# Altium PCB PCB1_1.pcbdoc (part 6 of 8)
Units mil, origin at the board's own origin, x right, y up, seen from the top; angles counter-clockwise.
Board outline 3937.01 x 3346.46 mil, 6 copper layers (Top Layer, Signal-1, SIG, POWER, Signal-4, Bottom Layer), stack 60.565 mil thick; 256 components, 201 nets, 1360 pads, 815 vias.
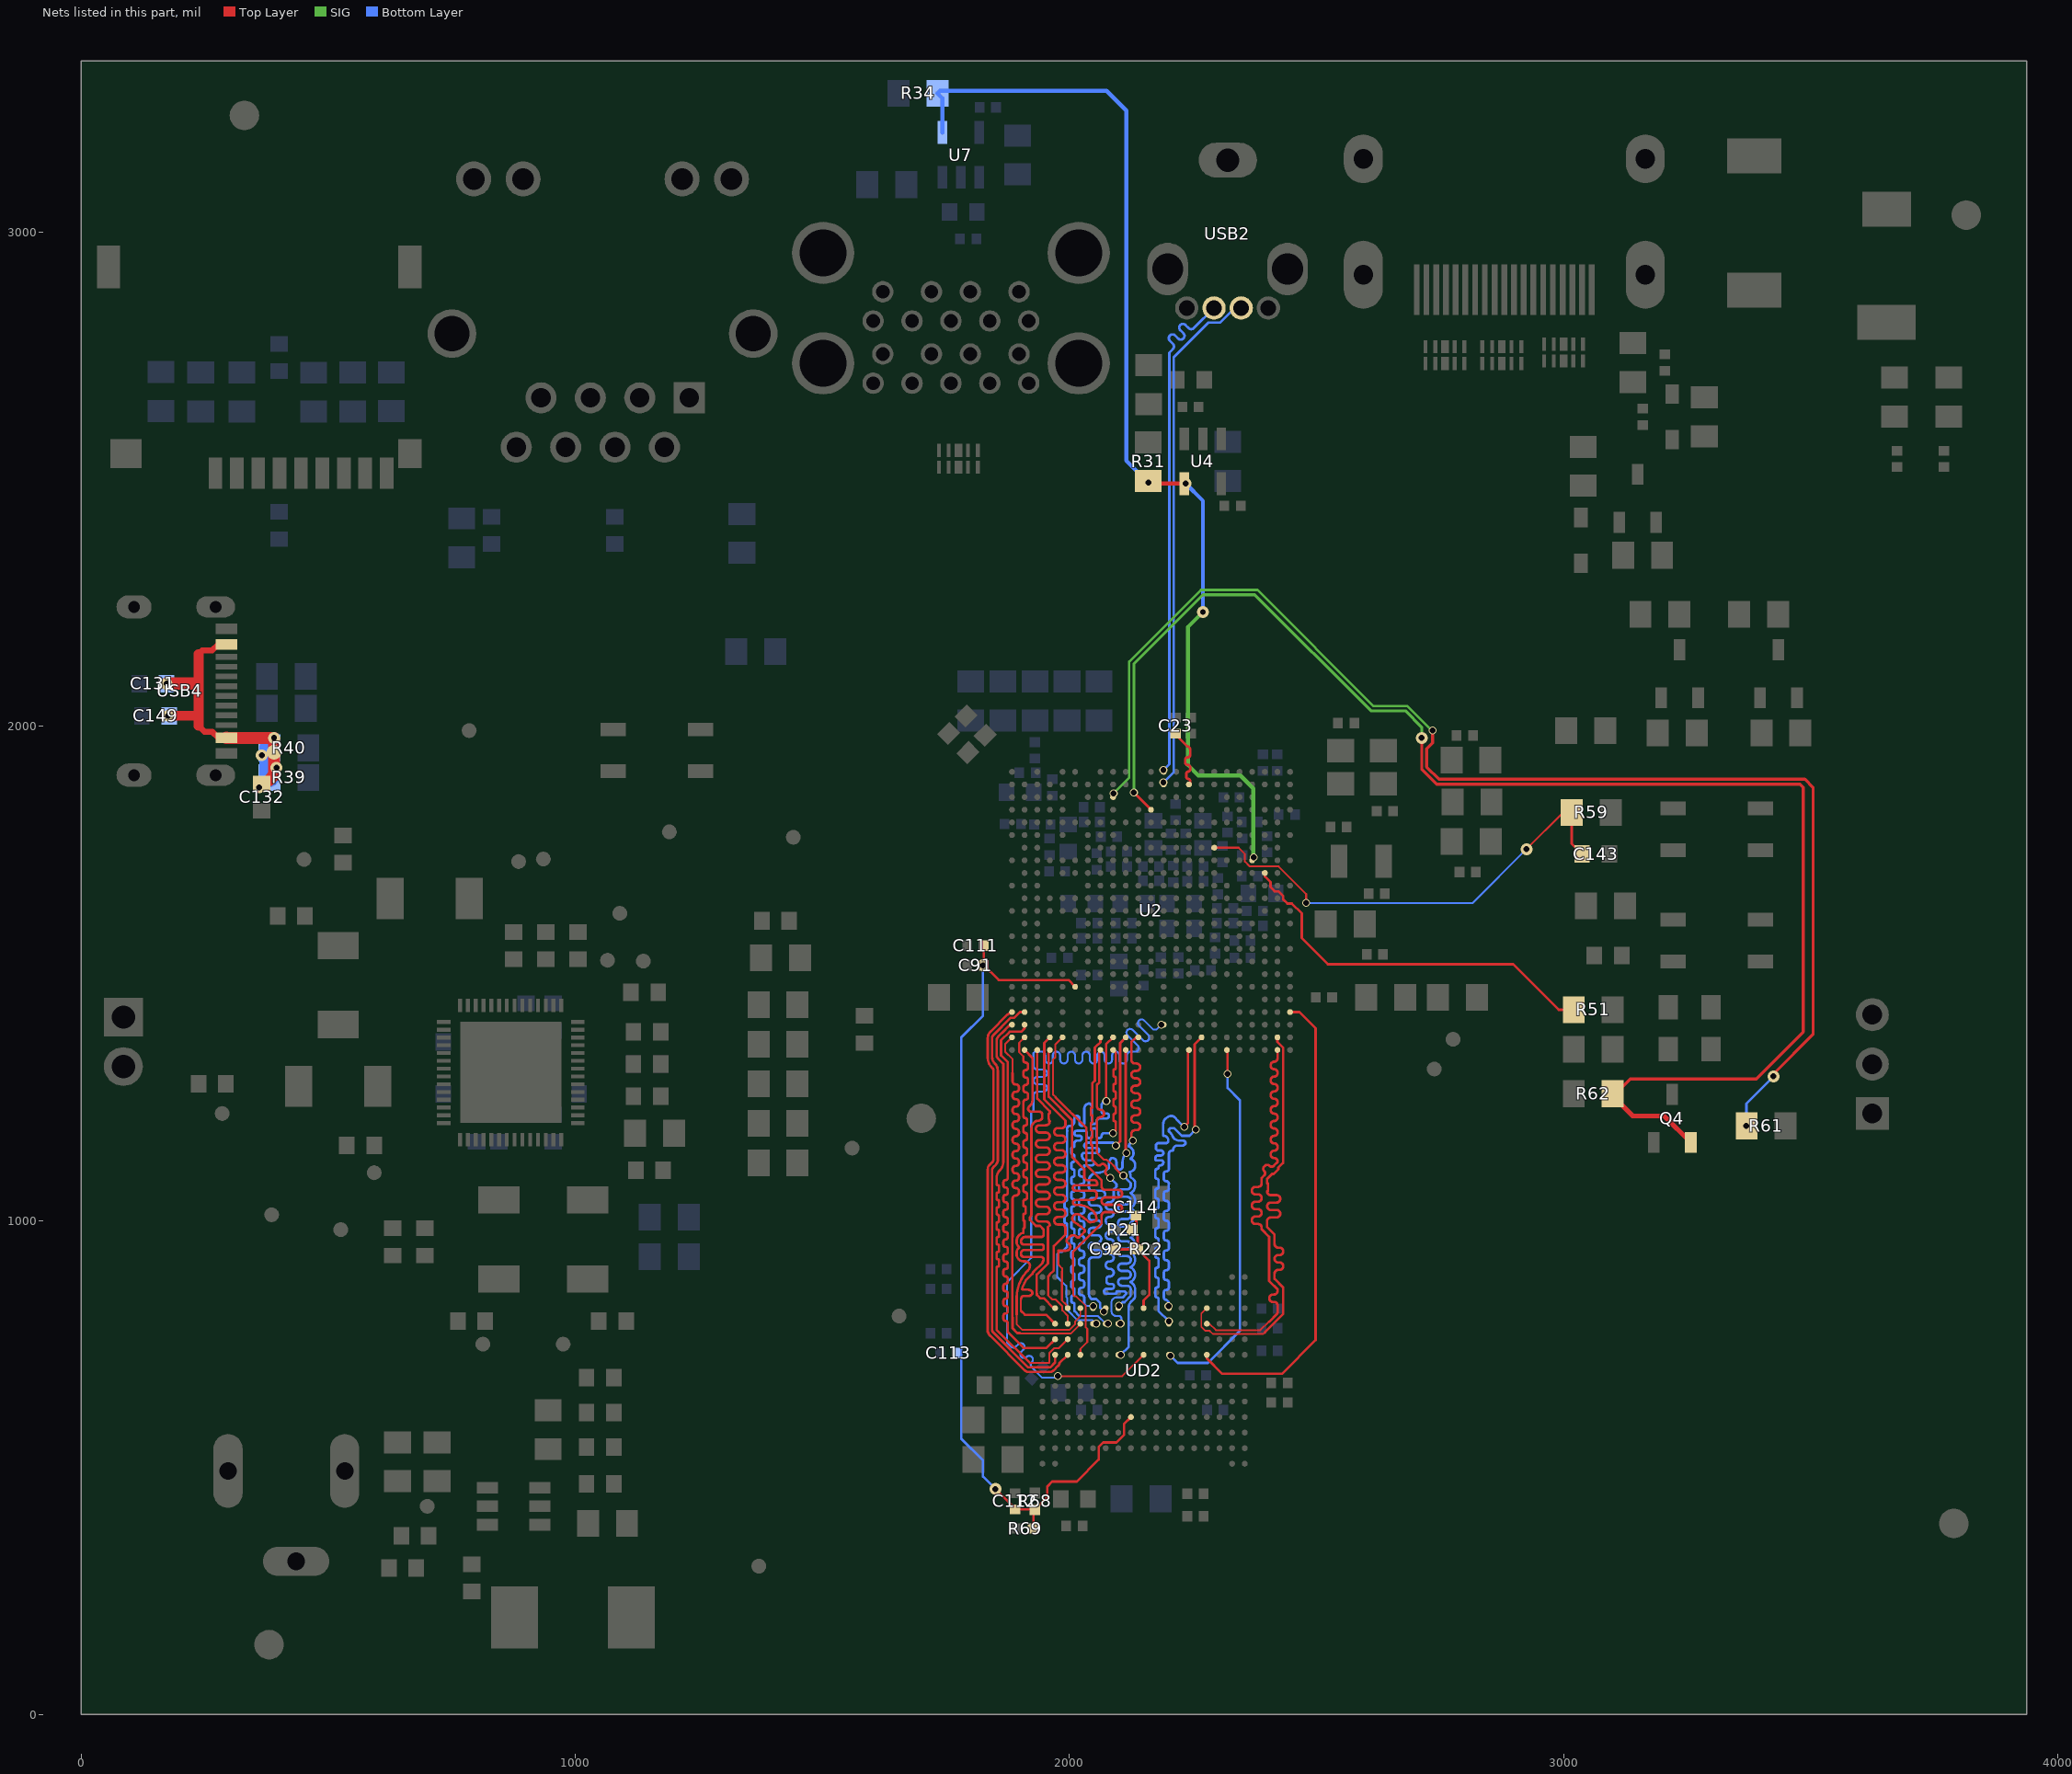
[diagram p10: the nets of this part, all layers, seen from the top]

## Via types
v1: diameter 16, hole 12, Top Layer to Bottom Layer, 426 vias
v2: diameter 24, hole 12, Top Layer to Bottom Layer, 385 vias
v3: diameter 34, hole 12, Top Layer to Bottom Layer, 2 vias
v4: diameter 30, hole 12, Top Layer to Bottom Layer, 2 vias

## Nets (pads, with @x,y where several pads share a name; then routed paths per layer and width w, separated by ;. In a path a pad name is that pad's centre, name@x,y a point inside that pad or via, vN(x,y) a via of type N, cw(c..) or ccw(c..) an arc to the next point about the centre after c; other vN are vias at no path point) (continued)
SDQ20: U2.AC9 UD2.F10 | length 857.1
  Top Layer w5: U2.AC9@2088.23,1344.96 2093.41,1339.78 2093.41,1308.09 cw(c2091.26,1308.09) 2091.26,1305.94 ccw(c2091.26,1303.78) 2089.1,1303.78 2089.1,1293.09 ccw(c2091.26,1293.09) 2091.26,1290.94 cw(c2091.26,1288.78) 2093.41,1288.78 2093.41,1278.09 cw(c2091.26,1278.09) 2091.26,1275.94 ccw(c2091.26,1273.78) 2089.1,1273.78 2089.1,1263.09 ccw(c2091.26,1263.09) 2091.26,1260.94 cw(c2091.26,1258.78) 2093.41,1258.78 2093.41,1248.09 cw(c2091.26,1248.09) 2091.26,1245.94 ccw(c2091.26,1243.78) 2089.1,1243.78 2089.1,1233.09 ccw(c2091.26,1233.09) 2091.26,1230.94 cw(c2091.26,1228.78) 2093.41,1228.78 2093.41,1218.09 cw(c2091.26,1218.09) 2091.26,1215.94 ccw(c2091.26,1213.78) 2089.1,1213.78 2089.1,1203.09 ccw(c2091.26,1203.09) 2091.26,1200.94 cw(c2091.26,1198.78) 2093.41,1198.78 2093.41,1181.46 v1(2088.41,1176.46)
  Bottom Layer w4: 2020,806.46 2057.63,806.46 2073.14,790.94 v1(2078.23,790.94)
  Bottom Layer w5: 2020,806.46 2010,816.46 2010,830.28 ccw(c2007,830.28) 2007,833.28 cw(c2007,836.28) 2004,836.28 2004,845.28 cw(c2007,845.28) 2007,848.28 ccw(c2007,851.28) 2010,851.28 2010,860.28 ccw(c2007,860.28) 2007,863.28 cw(c2007,866.28) 2004,866.28 2004,875.28 cw(c2007,875.28) 2007,878.28 ccw(c2007,881.28) 2010,881.28 2010,890.28 ccw(c2007,890.28) 2007,893.28 cw(c2007,896.28) 2004,896.28 2004,905.28 cw(c2007,905.28) 2007,908.28 ccw(c2007,911.28) 2010,911.28 2010,920.28 ccw(c2007,920.28) 2007,923.28 cw(c2007,926.28) 2004,926.28 2004,935.28 cw(c2007,935.28) 2007,938.28 ccw(c2007,941.28) 2010,941.28 2010,950.28 ccw(c2007,950.28) 2007,953.28 cw(c2007,956.28) 2004,956.28 2004,965.28 cw(c2007,965.28) 2007,968.28 ccw(c2007,971.28) 2010,971.28 2010,980.28 ccw(c2007,980.28) 2007,983.28 cw(c2007,986.28) 2004,986.28 2004,995.28 cw(c2007,995.28) 2007,998.28 ccw(c2007,1001.28) 2010,1001.28 2010,1010.28 ccw(c2007,1010.28) 2007,1013.28 cw(c2007,1016.28) 2004,1016.28 2004,1025.28 cw(c2007,1025.28) 2007,1028.28 ccw(c2007,1031.28) 2010,1031.28 2010,1040.28 ccw(c2007,1040.28) 2007,1043.28 cw(c2007,1046.28) 2004,1046.28 2004,1055.28 cw(c2007,1055.28) 2007,1058.28 ccw(c2007,1061.28) 2010,1061.28 2010,1070.28 ccw(c2007,1070.28) 2007,1073.28 cw(c2007,1076.28) 2004,1076.28 2004,1085.28 cw(c2007,1085.28) 2007,1088.28 ccw(c2007,1091.28) 2010,1091.28 2010,1100.28 ccw(c2007,1100.28) 2007,1103.28 cw(c2007,1106.28) 2004,1106.28 2004,1115.28 cw(c2007,1115.28) 2007,1118.28 ccw(c2007,1121.28) 2010,1121.28 2010,1130.28 ccw(c2007,1130.28) 2007,1133.28 cw(c2007,1136.28) 2004,1136.28 2004,1145.28 cw(c2007,1145.28) 2007,1148.28 ccw(c2007,1151.28) 2010,1151.28 2010,1156.46 cw(c2015,1156.46) 2015,1161.46 2020,1161.46 ccw(c2020,1166.46) 2025,1166.46 ccw(c2020,1166.46) 2020,1171.46 2015,1171.46 cw(c2015,1176.46) 2010,1176.46 cw(c2015,1176.46) 2015,1181.46 2030,1181.46 cw(c2030,1176.46) 2035,1176.46 2035,1171.46 ccw(c2040,1171.46) 2040,1166.46 ccw(c2040,1171.46) 2045,1171.46 2045,1181.46 cw(c2050,1181.46) 2050,1186.46 cw(c2050,1181.46) 2055,1181.46 2055,1171.46 ccw(c2060,1171.46) 2060,1166.46 ccw(c2060,1171.46) 2065,1171.46 cw(c2070,1171.46) 2070,1176.46 v1(2088.41,1176.46)
SDQ21: U2.AB9 UD2.E10 | length 853.4
  Top Layer w5: v1(2074.6,1241.46) 2074.04,1242.02 2074.04,1356.37 U2.AB9@2088.23,1370.55
  Bottom Layer w4: 1985,936.46 1980,936.46 1975,931.46 1975,885.74 1993.34,867.4 1993.34,845.24 1995.5,843.08 1995.5,818.94 2016.48,797.96 2046.93,797.96 v1(2054.09,790.8)
  Bottom Layer w5: 1985,936.46 1994.77,946.22 1994.77,991.95 ccw(c1992.38,991.95) 1992.38,994.34 cw(c1992.38,996.72) 1990,996.72 1990,1006.95 cw(c1992.38,1006.95) 1992.38,1009.34 ccw(c1992.38,1011.72) 1994.77,1011.72 1994.77,1021.95 ccw(c1992.38,1021.95) 1992.38,1024.34 cw(c1992.38,1026.72) 1990,1026.72 1990,1036.95 cw(c1992.38,1036.95) 1992.38,1039.34 ccw(c1992.38,1041.72) 1994.77,1041.72 1994.77,1180.22 1995.5,1180.96 ccw(c1995,1180.96) 1995,1181.46 1995,1185.46 cw(c2001,1185.46) 2001,1191.46 ccw(c2001,1200.46) 2010,1200.46 2010,1206.46 cw(c2015,1206.46) 2015,1211.46 cw(c2015,1206.46) 2020,1206.46 2020,1196.46 ccw(c2025,1196.46) 2025,1191.46 ccw(c2025,1196.46) 2030,1196.46 2030,1226.46 cw(c2040,1226.46) 2040,1236.46 cw(c2040,1231.46) 2045,1231.46 2045,1197.52 ccw(c2047.56,1197.52) 2045.75,1195.71 2050.75,1195.71 ccw(c2050.75,1199.96) 2055,1199.96 cw(c2061.5,1199.96) 2061.5,1206.46 2075,1206.46 ccw(c2075,1211.46) 2080,1211.46 ccw(c2075,1211.46) 2075,1216.46 2069,1216.46 cw(c2069,1220.46) 2065,1220.46 2065,1231.86 cw(c2074.6,1231.86) v1(2074.6,1241.46)
SDQ22: U2.AC10 UD2.F11 | length 849.3
  Top Layer w4: v1(2069.81,815.39) 2073.23,818.8 UD2.F11@2073.23,822.44
  Top Layer w5: U2.AC10@2113.82,1344.96 2113.82,1137.64 v1(2115,1136.46)
  Bottom Layer w5: v1(2069.81,815.39) 2062.1,823.11 2062.1,832.57 2053.9,840.77 2044.43,840.77 cw(c2057.29,853.63) 2039.1,853.63 2039.1,917.55 cw(c2046.6,917.55) 2046.6,925.05 2056.74,925.05 ccw(c2056.74,932.55) 2056.74,940.05 2046.6,940.05 cw(c2046.6,947.55) 2046.6,955.05 2056.74,955.05 ccw(c2056.74,962.55) 2056.74,970.05 2046.6,970.05 cw(c2046.6,977.55) 2046.6,985.05 2056.74,985.05 ccw(c2056.74,992.55) 2056.74,1000.05 2046.6,1000.05 cw(c2046.6,1007.55) 2046.6,1015.05 2056.74,1015.05 ccw(c2056.74,1022.55) 2056.74,1030.05 2046.6,1030.05 cw(c2046.6,1037.55) 2046.6,1045.05 2064.72,1045.05 ccw(c2064.72,1052.55) 2064.72,1060.05 2046.6,1060.05 cw(c2046.6,1067.55) 2039.1,1067.55 2039.1,1079.39 cw(c2056.18,1079.39) 2044.1,1091.46 cw(c2056.18,1079.39) 2056.18,1096.46 2056.94,1096.46 ccw(c2056.94,1127.99) 2079.24,1105.69 cw(c2081.08,1103.85) 2080,1106.22 2080,1114.39 cw(c2097.07,1114.39) 2085,1126.46 2086.46,1126.46 cw(c2086.46,1117.92) 2092.5,1123.96 cw(c2086.46,1117.92) 2095,1117.92 2095,1108.96 ccw(c2101.04,1108.96) 2096.77,1104.69 ccw(c2101.04,1108.96) 2101.04,1102.92 ccw(c2101.04,1108.96) 2105.3,1104.69 2106.19,1105.57 ccw(c2104.05,1107.71) 2107.07,1107.71 2107.07,1117.31 cw(c2134.14,1117.31) v1(2115,1136.46)
SDQ23: U2.AB10 UD2.E11 | length 843
  Top Layer w5: v1(2094.09,1151.46) 2102.41,1159.78 2102.41,1358.87 2113.82,1370.28 U2.AB10@2113.82,1370.55
  Bottom Layer w4: 2030,831.46 2034.69,826.77 v1(2048.1,826.77)
  Bottom Layer w5: 2030,831.46 2030,843.19 ccw(c2024.5,843.19) 2024.5,848.69 cw(c2024.5,854.19) 2019,854.19 2019,858.19 cw(c2024.5,858.19) 2024.5,863.69 ccw(c2024.5,869.19) 2030,869.19 2030,873.19 ccw(c2024.5,873.19) 2024.5,878.69 cw(c2024.5,884.19) 2019,884.19 2019,888.19 cw(c2024.5,888.19) 2024.5,893.69 ccw(c2024.5,899.19) 2030,899.19 2030,903.19 ccw(c2024.5,903.19) 2024.5,908.69 cw(c2024.5,914.19) 2019,914.19 2019,918.19 cw(c2024.5,918.19) 2024.5,923.69 ccw(c2024.5,929.19) 2030,929.19 2030,933.19 ccw(c2024.5,933.19) 2024.5,938.69 cw(c2024.5,944.19) 2019,944.19 2019,948.19 cw(c2024.5,948.19) 2024.5,953.69 ccw(c2024.5,959.19) 2030,959.19 2030,963.19 ccw(c2024.5,963.19) 2024.5,968.69 cw(c2024.5,974.19) 2019,974.19 2019,978.19 cw(c2024.5,978.19) 2024.5,983.69 ccw(c2024.5,989.19) 2030,989.19 2030,993.19 ccw(c2024.5,993.19) 2024.5,998.69 cw(c2024.5,1004.19) 2019,1004.19 2019,1008.19 cw(c2024.5,1008.19) 2024.5,1013.69 ccw(c2024.5,1019.19) 2030,1019.19 2030,1023.19 ccw(c2024.5,1023.19) 2024.5,1028.69 cw(c2024.5,1034.19) 2019,1034.19 2019,1038.19 cw(c2024.5,1038.19) 2024.5,1043.69 ccw(c2024.5,1049.19) 2030,1049.19 2030,1053.19 ccw(c2024.5,1053.19) 2024.5,1058.69 cw(c2024.5,1064.19) 2019,1064.19 2019,1068.19 cw(c2024.5,1068.19) 2024.5,1073.69 ccw(c2024.5,1079.19) 2030,1079.19 2030,1083.19 ccw(c2024.5,1083.19) 2024.5,1088.69 cw(c2024.5,1094.19) 2019,1094.19 2019,1098.19 cw(c2024.5,1098.19) 2024.5,1103.69 ccw(c2024.5,1109.19) 2030,1109.19 2030,1111.46 2045,1111.46 ccw(c2045,1116.46) 2050,1116.46 ccw(c2045,1116.46) 2045,1121.46 2035,1121.46 cw(c2035,1131.46) 2025,1131.46 cw(c2030,1131.46) 2030,1136.46 2055,1136.46 ccw(c2055,1141.46) 2060,1141.46 ccw(c2055,1141.46) 2055,1146.46 2035,1146.46 cw(c2035,1151.46) 2030,1151.46 cw(c2035,1151.46) 2035,1156.46 2036,1157.46 2088.09,1157.46 v1(2094.09,1151.46)
SDQ24: U2.Y1 UD2.C8 | length 888.7
  Top Layer w5: U2.Y1@1883.5,1421.73 1883.5,1419.33 1881.16,1419.33 ccw(c1881.16,1410.33) 1874.79,1416.69 1839.78,1381.67 ccw(c1852.5,1368.95) 1834.5,1368.95 1834.5,1328.89 ccw(c1861.02,1328.89) 1842.27,1310.14 1845.22,1307.19 cw(c1834.8,1303.09) 1846,1303.09 1846,1123.53 cw(c1837.93,1123.53) 1843.64,1117.82 1842.42,1116.6 ccw(c1855,1100.42) 1840.51,1114.92 ccw(c1855,1100.42) 1838.82,1113.01 1838.68,1112.86 ccw(c1848.74,1102.79) 1834.5,1102.79 1834.5,775.54 ccw(c1837.42,775.54) 1835.36,773.47 ccw(c1852.5,778.95) 1839.78,766.22 1909.91,696.09 ccw(c1916.27,702.46) 1916.27,693.46 1961,693.46 ccw(c1961,702.46) 1967.36,696.09 1977.23,705.96 ccw(c1970.87,712.32) 1979.81,711.3 1980.02,711.3 1996.46,727.75 UD2.C8@1996.46,727.95
SDQ25: U2.Y2 UD2.B8 | length 866.7
  Top Layer w5: U2.Y2@1909.09,1421.73 1899.63,1421.73 1888.23,1410.33 1881.16,1410.33 1846.14,1375.31 ccw(c1852.5,1368.95) 1843.5,1368.95 1843.5,1330.84 ccw(c1862.56,1330.84) 1849.08,1317.37 cw(c1834.8,1303.09) 1855,1303.09 1855,1123.53 cw(c1837.93,1123.53) 1850,1111.46 1848.33,1109.79 ccw(c1855,1100.42) 1846.87,1108.55 ccw(c1855,1100.42) 1845.64,1107.1 1845.04,1106.5 ccw(c1848.74,1102.79) 1843.5,1102.79 1843.5,778.95 ccw(c1852.5,778.95) 1846.14,772.59 1916.27,702.46 1961,702.46 1970.87,712.32 UD2.B8@1970.87,727.95
SDQ26: U2.AA1 UD2.C9 | length 875.6
  Top Layer w4: 1920,711.46 1957.98,711.46 ; 1958.63,712.1 ccw(c1957.06,713.67) 1959.28,713.67 1959.28,731.78 1968.95,741.46 1978.46,741.46 UD2.C9@1996.46,759.45
  Top Layer w5: U2.AA1@1883.5,1396.14 1879.7,1396.14 1870,1386.44 1870,1385.9 1855.14,1371.05 ccw(c1861.5,1364.68) 1852.5,1364.68 1852.5,1333.95 ccw(c1861.5,1333.95) 1855.14,1327.59 1866.02,1316.71 1866.02,1118.03 cw(c1842.95,1118.03) 1859.26,1101.72 ccw(c1875.57,1085.41) 1852.5,1085.41 1852.5,1073.73 ccw(c1854.91,1073.73) 1854.91,1071.32 cw(c1854.91,1068.92) 1857.32,1068.92 1857.32,1058.73 cw(c1854.91,1058.73) 1854.91,1056.32 ccw(c1854.91,1053.92) 1852.5,1053.92 1852.5,1043.73 ccw(c1854.91,1043.73) 1854.91,1041.32 cw(c1854.91,1038.92) 1857.32,1038.92 1857.32,1028.73 cw(c1854.91,1028.73) 1854.91,1026.32 ccw(c1854.91,1023.92) 1852.5,1023.92 1852.5,1013.73 ccw(c1854.91,1013.73) 1854.91,1011.32 cw(c1854.91,1008.92) 1857.32,1008.92 1857.32,998.73 cw(c1854.91,998.73) 1854.91,996.32 ccw(c1854.91,993.92) 1852.5,993.92 1852.5,983.73 ccw(c1854.91,983.73) 1854.91,981.32 cw(c1854.91,978.92) 1857.32,978.92 1857.32,968.73 cw(c1854.91,968.73) 1854.91,966.32 ccw(c1854.91,963.92) 1852.5,963.92 1852.5,953.73 ccw(c1854.91,953.73) 1854.91,951.32 cw(c1854.91,948.92) 1857.32,948.92 1857.32,938.73 cw(c1854.91,938.73) 1854.91,936.32 ccw(c1854.91,933.92) 1852.5,933.92 1852.5,923.73 ccw(c1854.91,923.73) 1854.91,921.32 cw(c1854.91,918.92) 1857.32,918.92 1857.32,908.73 cw(c1854.91,908.73) 1854.91,906.32 ccw(c1854.91,903.92) 1852.5,903.92 1852.5,778.95 1920,711.46
SDQ27: U2.AA2 UD2.B9 | length 877.7
  Top Layer w5: U2.AA2@1909.09,1396.14 1909.09,1388.62 1902.43,1381.96 1878.78,1381.96 1861.5,1364.68 1861.5,1333.95 1875.02,1320.44 1875.02,1085.99 cw(c1870.65,1085.99) 1870.65,1081.62 ccw(c1870.65,1077.26) 1866.28,1077.26 1866.28,1070.99 ccw(c1870.65,1070.99) 1870.65,1066.62 cw(c1870.65,1062.26) 1875.02,1062.26 1875.02,1055.99 cw(c1870.65,1055.99) 1870.65,1051.62 ccw(c1870.65,1047.26) 1866.28,1047.26 1866.28,1040.99 ccw(c1870.65,1040.99) 1870.65,1036.62 cw(c1870.65,1032.26) 1875.02,1032.26 1875.02,1025.99 cw(c1870.65,1025.99) 1870.65,1021.62 ccw(c1870.65,1017.26) 1866.28,1017.26 1866.28,1010.99 ccw(c1870.65,1010.99) 1870.65,1006.62 cw(c1870.65,1002.26) 1875.02,1002.26 1875.02,995.99 cw(c1870.65,995.99) 1870.65,991.62 ccw(c1870.65,987.26) 1866.28,987.26 1866.28,980.99 ccw(c1870.65,980.99) 1870.65,976.62 cw(c1870.65,972.26) 1875.02,972.26 1875.02,965.99 cw(c1870.65,965.99) 1870.65,961.62 ccw(c1870.65,957.26) 1866.28,957.26 1866.28,950.99 ccw(c1870.65,950.99) 1870.65,946.62 cw(c1870.65,942.26) 1875.02,942.26 1875.02,935.99 cw(c1870.65,935.99) 1870.65,931.62 ccw(c1870.65,927.26) 1866.28,927.26 1866.28,920.99 ccw(c1870.65,920.99) 1870.65,916.62 cw(c1870.65,912.26) 1875.02,912.26 1875.02,905.99 cw(c1870.65,905.99) 1870.65,901.62 ccw(c1870.65,897.26) 1866.28,897.26 1866.28,890.99 ccw(c1870.65,890.99) 1870.65,886.62 cw(c1870.65,882.26) 1875.02,882.26 1875.02,875.99 cw(c1870.65,875.99) 1870.65,871.62 ccw(c1870.65,867.26) 1866.28,867.26 1866.28,860.99 ccw(c1870.65,860.99) 1870.65,856.62 cw(c1870.65,852.26) 1875.02,852.26 1875.02,845.99 cw(c1870.65,845.99) 1870.65,841.62 ccw(c1870.65,837.26) 1866.28,837.26 1866.28,830.99 ccw(c1870.65,830.99) 1870.65,826.62 cw(c1870.65,822.26) 1875.02,822.26 1875.02,815.99 cw(c1870.65,815.99) 1870.65,811.62 ccw(c1870.65,807.26) 1866.28,807.26 1866.28,800.99 ccw(c1870.65,800.99) 1870.65,796.62 cw(c1870.65,792.26) 1875.02,792.26 1875.02,773.61 1906.68,741.95 1915.17,741.95 ccw(c1918.68,756.54) 1922.18,741.95 1953.37,741.95 UD2.B9@1970.87,759.45
SDQ28: U2.AC2 UD2.B10 | length 883.9
  Top Layer w4: 1901.75,816.68 1901.5,816.93 1901.5,840.57 1901.75,840.82
  Top Layer w4.5: 1901.75,816.68 1902,816.43 ; 1901.75,840.82 1902,841.07
  Top Layer w5: 1902,816.43 1909.49,808.94 1952.87,808.94 UD2.B10@1970.87,790.94 ; 1902,841.07 cw(c1908.04,841.07) 1903.77,845.34 cw(c1908.04,841.07) 1908.04,847.11 1917.58,847.11 ccw(c1917.58,854.53) 1922.83,849.28 1924.33,850.79 ccw(c1922.73,852.4) 1924.94,851.87 cw(c1933.87,852.98) 1924.87,852.98 ccw(c1919.14,852.98) 1923.19,857.03 ccw(c1916.58,850.42) 1916.58,859.77 1906.25,859.77 cw(c1906.25,862.79) 1904.12,860.66 ; 1904.14,860.65 cw(c1971.13,843.57) 1911.22,878.06 1925.04,891.88 cw(c1933.87,890.16) 1927.51,896.52 1944.92,913.93 ccw(c1942.88,915.97) 1945.76,915.97 ccw(c1941.49,920.24) 1947.53,920.24 1947.53,921.49 ccw(c1944.51,921.49) 1946.65,923.62 1945.76,924.5 ccw(c1941.49,920.24) 1941.49,926.27 1907.11,926.27 cw(c1907.11,931.36) 1903.51,927.76 cw(c1907.11,931.36) 1902.02,931.36 1902.02,933.96 cw(c1908.05,933.96) 1903.78,938.22 cw(c1908.05,933.96) 1908.05,939.99 1942.63,939.99 ccw(c1942.63,945.72) 1946.68,941.67 ccw(c1944.63,943.72) 1947.53,943.72 1947.53,947.73 ccw(c1944.64,947.73) 1946.68,949.77 1945.84,950.62 ccw(c1943.81,948.59) 1943.81,951.46 1907.07,951.46 cw(c1907.07,956.46) 1903.54,952.92 cw(c1907.07,956.46) 1902.07,956.46 1902.07,957.92 cw(c1910.61,957.92) 1904.57,963.96 cw(c1910.61,957.92) 1910.61,966.46 1942.5,966.46 ccw(c1942.5,972.49) 1946.77,968.22 ccw(c1944.93,970.06) 1947.53,970.06 1947.53,981.46 1940.24,988.75 1931.94,988.75 1920,1000.69 1920,1006.46 ccw(c1912.96,1013.5) 1922.92,1013.5 1922.92,1186.62 cw(c1937.75,1186.62) 1927.26,1197.11 1929.43,1199.28 cw(c1934.68,1194.04) 1934.68,1201.46 ccw(c1934.68,1214.3) 1943.76,1205.22 ccw(c1940.77,1208.21) 1945,1208.21 1945,1213.96 ccw(c1938.96,1213.96) 1943.23,1218.22 ccw(c1938.96,1213.96) 1938.96,1219.99 1922.5,1219.99 cw(c1922.5,1226.03) 1918.23,1221.76 cw(c1922.5,1226.03) 1916.46,1226.03 cw(c1922.5,1226.03) 1918.23,1230.3 1920.61,1232.67 ccw(c1910.01,1243.27) 1925,1243.27 1925,1329.06 U2.AC2@1909.09,1344.96
SDQ29: U2.AC3 UD2.B11 | length 870.1
  Top Layer w5: U2.AC3@1934.69,1344.96 1934.69,1246.32 1960,1221 1960,1217.27 cw(c1959,1217.27) 1959,1216.27 ccw(c1959,1215.27) 1958,1215.27 1958,1205.58 cw(c1950,1201.46) 1959,1201.27 cw(c1959,1200.27) 1960,1200.27 cw(c1952.5,1200.27) 1952.5,1192.77 1952.35,1192.77 cw(c1950,1201.46) 1950,1192.46 1937.27,1192.46 ccw(c1939.42,1185.27) 1939.42,1177.77 1952.5,1177.77 cw(c1952.5,1170.27) 1952.5,1162.77 1939.42,1162.77 ccw(c1939.42,1155.27) 1939.42,1147.77 1952.5,1147.77 cw(c1952.5,1140.27) 1952.5,1132.77 1939.42,1132.77 ccw(c1939.42,1125.27) 1939.42,1117.77 1952.5,1117.77 cw(c1952.5,1110.27) 1952.5,1102.77 1939.42,1102.77 ccw(c1939.42,1095.27) 1939.42,1087.77 1952.5,1087.77 cw(c1952.5,1080.27) 1952.5,1072.77 1939.42,1072.77 ccw(c1939.42,1065.27) 1939.42,1057.77 1952.5,1057.77 cw(c1952.5,1050.27) 1952.5,1042.77 1939.42,1042.77 ccw(c1939.42,1035.27) 1939.42,1027.77 1952.5,1027.77 cw(c1952.5,1020.27) 1952.5,1012.77 1939.42,1012.77 ccw(c1939.42,1005.27) 1939.42,997.77 1952.5,997.77 cw(c1952.5,990.27) 1960,990.27 1956.53,986.8 1956.53,912.82 1933.87,890.16 1933.87,852.98 cw(c1925,851.46) 1933.87,849.93 1933.87,849.21 1940.55,842.53 1947.62,842.53 1967.71,822.44 UD2.B11@1970.87,822.44
SDQ30: U2.AC4 UD2.C11 | length 872.8
  Top Layer w4: 1977.27,928.73 1977.27,910.66 1985,902.93 1985,896.46 1984.87,896.32 1984.87,837.9 1993.55,829.22 1993.55,825.35 UD2.C11@1996.46,822.44
  Top Layer w5: U2.AC4@1960.28,1344.96 1957.87,1342.56 1957.87,1250.35 2005.27,1202.96 2005.27,1128.46 2030,1103.73 2030,1086.46 2035,1081.46 2050.95,1081.46 cw(c2050.95,1078.27) 2053.2,1080.52 2054.14,1079.59 cw(c2049.64,1075.09) 2056,1075.09 2056,1072.84 cw(c2055.09,1072.84) 2055.73,1072.19 cw(c2053.96,1073.96) 2053.96,1071.46 2012.37,1071.46 ccw(c2012.37,1065.72) 2008.32,1069.78 ccw(c2012.37,1065.72) 2006.64,1065.72 ccw(c2012.37,1065.72) 2008.32,1061.67 ccw(c2012.37,1065.72) 2012.37,1059.99 2048.96,1059.99 cw(c2048.96,1053.96) 2053.23,1058.22 cw(c2048.96,1053.96) 2055,1053.96 2055,1048.53 cw(c2050,1048.53) 2053.54,1044.99 cw(c2045,1053.53) 2045,1041.46 2012.07,1041.46 ccw(c2012.07,1036.46) 2008.54,1039.99 ccw(c2012.07,1036.46) 2007.07,1036.46 ccw(c2012.07,1036.46) 2008.54,1032.92 ccw(c2012.07,1036.46) 2012.07,1031.46 2016.72,1031.46 cw(c2016.72,987.31) 2047.93,1018.53 cw(c2030.86,1001.46) 2055,1001.46 cw(c2042.93,1013.53) 2042.93,996.46 2042.3,996.46 cw(c2042.3,1002.01) 2038.37,998.08 ccw(c2038.03,997.74) 2038.03,998.22 ccw(c1954.51,903.31) 2020,1011.46 ccw(c2015,1003.2) 2010,1011.46 ccw(c2014.54,1003.96) 2010,996.46 cw(c1944.51,888.3) 2030,981.46 cw(c2027.71,978.96) 2030,976.46 ccw(c2141.56,854.9) 2020,966.46 cw(c2017.5,968.75) 2015,966.46 ccw(c2007.5,959.57) 2000,966.46 cw(c1939.22,1022.24) 1995,961.46 ccw(c1997.29,958.96) 1995,956.46 cw(c1939.22,895.68) 2000,951.46 cw(c1994.75,946.64) 2000.68,942.69 ccw(c2007.17,936.46) 1999.79,941.6 cw(c1992.85,948.55) 1992.85,938.73 1977.27,938.73 1977.27,928.73
SDQ31: U2.AB4 UD2.C10 | length 865.4
  Top Layer w4: 1956.87,886.86 1956.87,848.14 1965.07,839.94 1971.52,839.94 1985.55,825.91 1985.55,817.92 1996.46,807.02 UD2.C10@1996.46,790.94
  Top Layer w5: 1956.87,886.86 1959.46,889.45 1959.46,890.16 1968.27,898.97 1968.27,947.91 1991.77,971.42 1991.77,984.34 ccw(c1984.27,984.34) 1984.27,991.84 1976.5,991.84 cw(c1976.5,999.34) 1976.5,1006.84 1984.27,1006.84 ccw(c1984.27,1014.34) 1984.27,1021.84 1976.5,1021.84 cw(c1976.5,1029.34) 1976.5,1036.84 1984.27,1036.84 ccw(c1984.27,1044.34) 1984.27,1051.84 1976.5,1051.84 cw(c1976.5,1059.34) 1976.5,1066.84 1984.27,1066.84 ccw(c1984.27,1074.34) 1984.27,1081.84 1976.5,1081.84 cw(c1976.5,1089.34) 1976.5,1096.84 1984.27,1096.84 ccw(c1984.27,1104.34) 1984.27,1111.84 1976.5,1111.84 cw(c1976.5,1119.34) 1976.5,1126.84 1984.27,1126.84 ccw(c1984.27,1134.34) 1984.27,1141.84 1976.5,1141.84 cw(c1976.5,1149.34) 1976.5,1156.84 1984.27,1156.84 ccw(c1984.27,1164.34) 1984.27,1171.84 1976.5,1171.84 cw(c1976.5,1179.34) 1976.5,1186.84 1984.27,1186.84 ccw(c1984.27,1194.34) 1991.77,1194.34 1991.77,1201.96 1948.87,1244.86 1948.87,1359.15 U2.AB4@1960.28,1370.55
SDQM0: U2.AC18 UD2.L8 | length 753.1
  Top Layer w5: U2.AC18@2318.54,1344.96 2320,1343.5 v1(2320,1296.46)
  Bottom Layer w5: v1(2204.39,726.17) 2219.1,711.46 2280,711.46 2345,776.46 2345,1242.93 2320,1267.93 v1(2320,1296.46)
SDQM1: U2.Y23 UD2.P8 | length 964.7
  Top Layer w5: UD2.P8@2277.95,727.95 2277.95,720.78 2309.18,689.55 2429.81,689.55 2498,757.74 2498,1388.94 2465.21,1421.73 U2.Y23@2446.5,1421.73
SDQM2: U2.AB11 UD2.G8 | length 854.9
  Top Layer w5: v1(2128.32,1161.46) 2125.22,1164.55 2125.22,1175.18 cw(c2132.72,1175.18) 2132.72,1182.68 2135.54,1182.68 ccw(c2135.54,1190.18) 2135.54,1197.68 2132.72,1197.68 cw(c2132.72,1205.18) 2132.72,1212.68 2135.54,1212.68 ccw(c2135.54,1220.18) 2135.54,1227.68 2132.72,1227.68 cw(c2132.72,1235.18) 2132.72,1242.68 2135.54,1242.68 ccw(c2135.54,1250.18) 2135.54,1257.68 2132.72,1257.68 cw(c2132.72,1265.18) 2132.72,1272.68 2135.54,1272.68 ccw(c2135.54,1280.18) 2135.54,1287.68 2132.72,1287.68 cw(c2132.72,1295.18) 2132.72,1302.68 2135.54,1302.68 ccw(c2135.54,1310.18) 2135.54,1317.68 2132.72,1317.68 cw(c2132.72,1325.18) 2125.22,1325.18 2125.22,1360.91 2134.87,1370.55 U2.AB11@2139.41,1370.55
  Bottom Layer w5: v1(2103.82,727.95) 2120,744.13 2120,823.13 cw(c2138.76,823.13) 2125.49,836.39 2130.36,841.26 ccw(c2124,847.62) 2133,847.62 2133,860.25 ccw(c2116.5,860.25) 2123.37,875.25 ccw(c2116.5,890.25) 2123.37,905.25 ccw(c2116.5,920.25) 2123.37,935.25 ccw(c2116.5,950.25) 2123.37,965.25 ccw(c2116.5,980.25) 2123.37,995.25 ccw(c2116.5,1010.25) 2123.37,1025.25 ccw(c2116.5,1040.25) 2123.37,1055.25 ccw(c2116.5,1070.25) 2133,1070.25 2133,1075.46 ccw(c2124,1075.46) 2130.36,1081.82 2123.4,1088.78 ccw(c2109,1090.46) 2121.38,1098 ccw(c2120.5,1110.47) 2133,1110.47 2133,1111.95 ccw(c2120,1111.95) 2123.26,1124.54 ccw(c2115,1136.46) 2120,1150.07 cw(c2123.35,1150.07) 2120.98,1152.44 2120.98,1154.12 v1(2128.32,1161.46)
SDQM3: U2.AB5 UD2.D8 | length 875.4
  Top Layer w3.5: 2013.45,846.46 2032.7,827.21 2032.7,783.75 2032.95,783.5
  Top Layer w4: 1971.68,1249.78 1966.37,1255.09 1966.37,1325.5 1971.18,1330.31 1971.18,1355.87 U2.AB5@1985.87,1370.55 ; 2007.17,936.46 2007.17,858.64 2007.36,858.45 2007.36,849.09 2010,846.46 2013.45,846.46 ; UD2.D8@2022.05,727.95 2022.05,739.65 2036.05,753.65 2036.05,780.41 2032.95,783.5
  Top Layer w5: 1971.68,1249.78 2000.5,1220.96 2000.5,1220.45 2008.99,1211.96 2009.5,1211.96 2034.4,1187.06 2034.4,1112.06 2065,1081.46 2065,1069.22 ccw(c2072.5,1069.22) 2072.5,1061.72 2098.9,1061.72 cw(c2098.9,1054.22) 2098.9,1046.72 2072.5,1046.72 ccw(c2072.5,1039.22) 2072.5,1031.72 2098.9,1031.72 cw(c2098.9,1024.22) 2098.9,1016.72 2072.5,1016.72 ccw(c2072.5,1009.22) 2065,1009.22 2065,994.29 2007.17,936.46
SDQS0N: U2.AB16 UD2.L11 | length 744
  Top Layer w5: v1(2255.58,1184.03) 2253.18,1186.43 2253.18,1356.37 U2.AB16@2267.36,1370.55
  Bottom Layer w5: v1(2200.32,826.58) 2200.32,835.08 2196.08,839.32 cw(c2196.08,844.42) 2190.97,844.42 2190.97,854.21 cw(c2196.08,854.21) 2196.08,859.32 ccw(c2196.08,864.42) 2201.18,864.42 2201.18,874.21 ccw(c2196.08,874.21) 2196.08,879.32 cw(c2196.08,884.42) 2190.97,884.42 2190.97,894.21 cw(c2196.08,894.21) 2196.08,899.32 ccw(c2196.08,904.42) 2201.18,904.42 2201.18,914.21 ccw(c2196.08,914.21) 2196.08,919.32 cw(c2196.08,924.42) 2190.97,924.42 2190.97,934.21 cw(c2196.08,934.21) 2196.08,939.32 ccw(c2196.08,944.42) 2201.18,944.42 2201.18,954.21 ccw(c2196.08,954.21) 2196.08,959.32 cw(c2196.08,964.42) 2190.97,964.42 2190.97,974.21 cw(c2196.08,974.21) 2196.08,979.32 ccw(c2196.08,984.42) 2201.18,984.42 2201.18,994.21 ccw(c2196.08,994.21) 2196.08,999.32 cw(c2196.08,1004.42) 2190.97,1004.42 2190.97,1014.21 cw(c2196.08,1014.21) 2196.08,1019.32 ccw(c2196.08,1024.42) 2201.18,1024.42 2201.18,1034.21 ccw(c2196.08,1034.21) 2196.08,1039.32 cw(c2196.08,1044.42) 2190.97,1044.42 2190.97,1054.21 cw(c2196.08,1054.21) 2196.08,1059.32 ccw(c2196.08,1064.42) 2201.18,1064.42 2200.99,1064.62 2200.99,1074.02 2201.18,1074.21 ccw(c2196.08,1074.21) 2196.08,1079.32 cw(c2196.08,1084.42) 2190.97,1084.42 2190.97,1094.21 cw(c2196.08,1094.21) 2196.08,1099.32 ccw(c2196.08,1104.42) 2201.18,1104.42 2201.18,1134.63 cw(c2208,1134.63) 2208,1141.46 ccw(c2208,1143.45) 2210,1143.45 cw(c2218,1143.45) 2218,1151.46 2227.41,1151.46 ccw(c2227.41,1160.87) 2234.07,1154.22 2234.54,1154.68 ccw(c2233.41,1155.8) 2235,1155.8 2235,1156.46 ccw(c2230,1156.46) 2230,1161.46 2222.67,1161.46 cw(c2222.67,1177.56) 2211.28,1166.17 ccw(c2210.37,1165.26) 2210.37,1166.55 ccw(c2190,1161.46) 2205,1176.15 ccw(c2204.7,1176.15) 2204.7,1176.46 2201.85,1179.3 cw(c2204.01,1181.46) 2200.96,1181.46 2200.96,1182.42 cw(c2205,1182.42) 2205,1186.46 2212.07,1186.46 2227.07,1171.46 2243,1171.46 v1(2255.58,1184.03)
SDQS0P: U2.AC15 UD2.L10 | length 744.6
  Top Layer w5: v1(2232.16,1189.16) 2240,1197 2240,1343.19 U2.AC15@2241.77,1344.96
  Bottom Layer w5: 2189.96,1171.5 2189.31,1172.15 2189.35,1195.81 2190,1196.46 cw(c2202.07,1196.46) 2193.54,1204.99 2195,1206.46 cw(c2207.07,1194.39) 2207.07,1211.46 cw(c2207.07,1204.39) 2212.07,1209.39 2220,1201.46 2220,1201.32 v1(2232.16,1189.16) ; 2190,1171.46 cw(c2190,1161.46) 2200,1161.46 cw(c2195,1161.46) 2195,1156.46 2180,1156.46 ccw(c2180,1151.46) 2175,1151.46 2175,1146.46 ccw(c2180,1146.46) 2180,1141.46 2185,1141.46 cw(c2185,1136.46) 2190,1136.46 cw(c2185,1136.46) 2185,1131.46 2179,1131.46 ccw(c2179,1126.46) 2174,1126.46 2174,1123.16 ccw(c2175.71,1123.16) 2174.5,1121.96 ccw(c2175.71,1123.16) 2175.71,1121.46 2185.77,1121.46 cw(c2185.77,1117.23) 2190,1117.23 cw(c2184.23,1117.23) 2184.23,1111.46 ccw(c2184.23,1107.23) 2180,1107.23 cw(c2177,1107.23) 2177,1104.23 ccw(c2177,1101.23) 2174,1101.23 2174,1087.23 ccw(c2177,1087.23) 2177,1084.23 cw(c2177,1081.23) 2180,1081.23 2180,1067.23 cw(c2177,1067.23) 2177,1064.23 ccw(c2177,1061.23) 2174,1061.23 2174,1047.23 ccw(c2177,1047.23) 2177,1044.23 cw(c2177,1041.23) 2180,1041.23 2180,1027.23 cw(c2177,1027.23) 2177,1024.23 ccw(c2177,1021.23) 2174,1021.23 2174,1007.23 ccw(c2177,1007.23) 2177,1004.23 cw(c2177,1001.23) 2180,1001.23 2180,987.23 cw(c2177,987.23) 2177,984.23 ccw(c2177,981.23) 2174,981.23 2174,967.23 ccw(c2177,967.23) 2177,964.23 cw(c2177,961.23) 2180,961.23 2180,947.23 cw(c2177,947.23) 2177,944.23 ccw(c2177,941.23) 2174,941.23 2174,927.23 ccw(c2177,927.23) 2177,924.23 cw(c2177,921.23) 2180,921.23 2180,907.23 cw(c2177,907.23) 2177,904.23 ccw(c2177,901.23) 2174,901.23 2174,887.23 ccw(c2177,887.23) 2177,884.23 cw(c2177,881.23) 2180,881.23 2180,867.23 cw(c2177,867.23) 2177,864.23 ccw(c2177,861.23) 2174,861.23 2174,847.23 ccw(c2177,847.23) 2177,844.23 cw(c2177,841.23) 2180,841.23 2180,817.13 v1(2201.18,795.94)
SDQS1N: U2.AB22 UD2.P11 | length 952.6
  Top Layer w3.5: UD2.P11@2277.95,822.44 2266.8,811.29 2266.8,784.66 2275,776.46 2283.96,776.46 2290.21,770.21 2392.09,770.21 2395,773.12
  Top Layer w5: 2395,773.12 2432.31,810.43 2432.31,864.7 2415,882.01 2415,892.38 cw(c2422.5,892.38) 2422.5,899.88 2425.07,899.88 ccw(c2425.07,907.38) 2425.07,914.88 2422.5,914.88 cw(c2422.5,922.38) 2422.5,929.88 2425.07,929.88 ccw(c2425.07,937.38) 2425.07,944.88 2422.5,944.88 cw(c2422.5,952.38) 2415,952.38 2415,971.46 2400,986.46 2400,998.64 cw(c2407.5,998.64) 2407.5,1006.14 2419.17,1006.14 ccw(c2419.17,1013.64) 2419.17,1021.14 2407.5,1021.14 cw(c2407.5,1028.64) 2407.5,1036.14 2419.17,1036.14 ccw(c2419.17,1043.64) 2419.17,1051.14 2407.5,1051.14 cw(c2407.5,1058.64) 2400,1058.64 cw(c2401,1058.64) 2401,1059.64 ccw(c2401,1060.64) 2402,1060.64 2402,1073.64 ccw(c2401,1073.64) 2401,1074.64 cw(c2401,1075.64) 2400,1075.64 2400,1084.29 2410.17,1094.45 cw(c2410.99,1093.62) 2411.82,1094.45 ccw(c2412.65,1095.28) 2413.48,1094.45 2422.43,1103.4 ccw(c2421.6,1104.23) 2422.43,1105.06 cw(c2423.26,1105.89) 2422.43,1106.71 2432.31,1116.6 2432.31,1349.68 2420.91,1361.09 U2.AB22@2420.91,1370.55
SDQS1P: U2.AC22 UD2.P10 | length 952.5
  Top Layer w3.5: UD2.P10@2277.95,790.94 2282.9,790.94 2296.14,777.71 2386.25,777.71 2403.21,794.67 2403.82,794.67
  Top Layer w5: 2403.82,794.67 2421.31,812.16 2421.31,827.5 ccw(c2413.81,827.5) 2413.81,835 2411.87,835 cw(c2411.87,842.5) 2411.87,850 2413.81,850 ccw(c2413.81,857.5) 2421.31,857.5 2421.31,860.15 2404,877.46 2404,966.9 2389,981.9 2389,985.33 ccw(c2381.5,985.33) 2381.5,992.83 2376.48,992.83 cw(c2376.48,1000.33) 2376.48,1007.83 2381.5,1007.83 ccw(c2381.5,1015.33) 2381.5,1022.83 2376.48,1022.83 cw(c2376.48,1030.33) 2376.48,1037.83 2381.5,1037.83 ccw(c2381.5,1045.33) 2381.5,1052.83 2376.48,1052.83 cw(c2376.48,1060.33) 2376.48,1067.83 2381.5,1067.83 ccw(c2381.5,1075.33) 2389,1075.33 2389,1086.01 2394,1091.02 ccw(c2389.52,1095.5) 2394,1099.98 cw(c2398.49,1104.46) 2394,1108.94 2395.65,1110.59 cw(c2400.13,1106.11) 2404.61,1110.59 ccw(c2409.09,1115.07) 2413.57,1110.59 2421.31,1118.32 2421.31,1119.11 ccw(c2414.26,1119.11) 2414.26,1126.16 cw(c2414.26,1133.21) 2407.21,1133.21 2407.21,1134.11 cw(c2414.26,1134.11) 2414.26,1141.16 ccw(c2414.26,1148.21) 2421.31,1148.21 2421.31,1149.11 ccw(c2414.26,1149.11) 2414.26,1156.16 cw(c2414.26,1163.21) 2407.21,1163.21 2407.21,1164.11 cw(c2414.26,1164.11) 2414.26,1171.16 ccw(c2414.26,1178.21) 2421.31,1178.21 2421.31,1179.11 ccw(c2414.26,1179.11) 2414.26,1186.16 cw(c2414.26,1193.21) 2407.21,1193.21 2407.21,1194.11 cw(c2414.26,1194.11) 2414.26,1201.16 ccw(c2414.26,1208.21) 2421.31,1208.21 2421.31,1209.11 ccw(c2414.26,1209.11) 2414.26,1216.16 cw(c2414.26,1223.21) 2407.21,1223.21 2407.21,1224.11 cw(c2414.26,1224.11) 2414.26,1231.16 ccw(c2414.26,1238.21) 2421.31,1238.21 2421.31,1239.11 ccw(c2414.26,1239.11) 2414.26,1246.16 cw(c2414.26,1253.21) 2407.21,1253.21 2407.21,1254.11 cw(c2414.26,1254.11) 2414.26,1261.16 ccw(c2414.26,1268.21) 2421.31,1268.21 2421.31,1269.11 ccw(c2414.26,1269.11) 2414.26,1276.16 cw(c2414.26,1283.21) 2407.21,1283.21 2407.21,1284.11 cw(c2414.26,1284.11) 2414.26,1291.16 ccw(c2414.26,1298.21) 2421.31,1298.21 2421.31,1299.11 ccw(c2414.26,1299.11) 2414.26,1306.16 cw(c2414.26,1313.21) 2407.21,1313.21 2407.21,1314.11 cw(c2414.26,1314.11) 2414.26,1321.16 ccw(c2414.26,1328.21) 2421.31,1328.21 2421.31,1344.56 U2.AC22@2420.91,1344.96
SDQS2N: U2.AC8 UD2.G11 | length 850.5
  Top Layer w4: 2055.5,1143.96 2055.5,1136.86 2069.41,1122.96 2075.06,1122.96 2081.42,1116.6 ccw(c2081.95,1117.13) 2082.48,1116.6 cw(c2083.01,1116.07) 2083.54,1116.6 2093.09,1107.05 cw(c2092.56,1106.52) 2093.09,1105.99 ccw(c2093.62,1105.46) 2093.09,1104.93 2107.56,1090.46 v1(2109,1090.46)
  Top Layer w5: 2055.5,1143.96 2055.5,1201.78 cw(c2062.75,1201.78) 2062.75,1209.03 ccw(c2062.75,1216.28) 2070,1216.28 2070,1216.78 ccw(c2062.75,1216.78) 2062.75,1224.03 cw(c2062.75,1231.28) 2055.5,1231.28 2055.5,1274.32 2060.23,1279.05 2060.23,1342.56 U2.AC8@2062.64,1344.96
  Bottom Layer w4: 2111.12,834.53 2124,847.41 2124,860.25
  Bottom Layer w5: v1(2099.93,827.44) 2107.02,834.53 2111.12,834.53 ; v1(2109,1090.46) 2124,1075.46 2124,1070.25 cw(c2116.5,1070.25) 2116.5,1062.75 2106,1062.75 ccw(c2106,1055.25) 2106,1047.75 2116.5,1047.75 cw(c2116.5,1040.25) 2116.5,1032.75 2106,1032.75 ccw(c2106,1025.25) 2106,1017.75 2116.5,1017.75 cw(c2116.5,1010.25) 2116.5,1002.75 2106,1002.75 ccw(c2106,995.25) 2106,987.75 2116.5,987.75 cw(c2116.5,980.25) 2116.5,972.75 2106,972.75 ccw(c2106,965.25) 2106,957.75 2116.5,957.75 cw(c2116.5,950.25) 2116.5,942.75 2106,942.75 ccw(c2106,935.25) 2106,927.75 2116.5,927.75 cw(c2116.5,920.25) 2116.5,912.75 2106,912.75 ccw(c2106,905.25) 2106,897.75 2116.5,897.75 cw(c2116.5,890.25) 2116.5,882.75 2106,882.75 ccw(c2106,875.25) 2106,867.75 2116.5,867.75 cw(c2116.5,860.25) 2124,860.25
SDQS2P: U2.AB8 UD2.G10 | length 850.2
  Top Layer w5: U2.AB8@2062.64,1370.55 2062.64,1360.55 2058.45,1356.37 2057.91,1356.37 2051.23,1349.68 2051.23,1282.78 2046.5,1278.05 2046.5,1229.22 cw(c2044.95,1229.22) 2044.95,1227.67 ccw(c2044.95,1226.12) 2043.4,1226.12 2043.4,1214.22 ccw(c2044.95,1214.22) 2044.95,1212.67 cw(c2044.95,1211.12) 2046.5,1211.12 2046.5,1199.22 cw(c2044.95,1199.22) 2044.95,1197.67 ccw(c2044.95,1196.12) 2043.4,1196.12 2043.4,1184.22 ccw(c2044.95,1184.22) 2044.95,1182.67 cw(c2044.95,1181.12) 2046.5,1181.12 2046.5,1169.22 cw(c2044.95,1169.22) 2044.95,1167.67 ccw(c2044.95,1166.12) 2043.4,1166.12 2043.4,1154.22 ccw(c2044.95,1154.22) 2044.95,1152.67 cw(c2044.95,1151.12) 2046.5,1151.12 2046.5,1121.84 2055.54,1112.81 ccw(c2059.51,1116.77) 2063.47,1112.81 cw(c2067.44,1108.84) 2071.41,1112.81 2074.08,1110.13 cw(c2070.11,1106.17) 2074.08,1102.2 ccw(c2078.05,1098.23) 2074.08,1094.26 v1(2082.44,1085.9)
  Bottom Layer w4: 2095,843.9 ccw(c2095,833.9) 2085,833.9 2085,824.69 ccw(c2098.82,822.44) 2085,820.2 2085,816.46 ccw(c2095,816.46) 2095,806.46 2100,806.46 cw(c2100,801.46) 2105,801.46 2105,792.55 v1(2103.39,790.94)
  Bottom Layer w5: v1(2082.44,1085.9) 2094.98,1073.37 2094.98,1068.22 2090.13,1063.37 2090.13,1060.17 2089.5,1059.54 2089.5,1044.54 cw(c2082,1044.54) 2082,1037.04 2080.73,1037.04 ccw(c2080.73,1029.54) 2080.73,1022.04 2082,1022.04 cw(c2082,1014.54) 2082,1007.04 2080.73,1007.04 ccw(c2080.73,999.54) 2080.73,992.04 2082,992.04 cw(c2082,984.54) 2082,977.04 2080.73,977.04 ccw(c2080.73,969.54) 2080.73,962.04 2082,962.04 cw(c2082,954.54) 2082,947.04 2080.73,947.04 ccw(c2080.73,939.54) 2080.73,932.04 2082,932.04 cw(c2082,924.54) 2082,917.04 2080.73,917.04 ccw(c2080.73,909.54) 2080.73,902.04 2082,902.04 cw(c2082,894.54) 2089.5,894.54 cw(c2081.42,894.54) 2081.42,886.46 2080,886.46 ccw(c2080,881.46) 2075,881.46 2075,876.46 ccw(c2080,876.46) 2080,871.46 2085,871.46 cw(c2085,866.46) 2090,866.46 cw(c2085,866.46) 2085,861.46 2075,861.46 ccw(c2075,856.46) 2070,856.46 ccw(c2075,856.46) 2075,851.46 2092.5,851.46 ccw(c2092.5,853.96) 2095,853.96 cw(c2097.5,853.96) 2097.5,856.46 2110,856.46 cw(c2110,851.46) 2115,851.46 2107.63,844.09 ccw(c2107.81,843.9) 2107.55,843.9 2095,843.9
SDQS3N: U2.AB2 UD2.D11 | length 873.5
  Top Layer w3.5: 1893,809.46 1893,791.59 1892.87,791.46 1892.87,790.25 1904.84,778.29 1999.27,778.29 2011.39,790.41 2011.39,795.36 2022.05,806.01 UD2.D11@2022.05,822.44
  Top Layer w4: 1906.89,1331.74 1898.19,1340.44 1898.19,1359.65 U2.AB2@1909.09,1370.55
  Top Layer w5: 1893,809.46 1893,843.57 cw(c1971.13,843.57) 1906.89,888.04 cw(c1971.13,843.57) 1915.88,898.82 ccw(c1905.95,908.76) 1920,908.76 ccw(c1913.48,908.76) 1918.09,913.37 ccw(c1908.66,903.93) 1908.66,917.27 1906.89,917.27 cw(c1907.11,931.36) 1897.14,921.4 cw(c1907.11,931.36) 1893.02,931.36 1893.02,933.96 cw(c1908.05,933.96) 1897.42,944.59 cw(c1908.05,933.96) 1898.39,945.47 cw(c1907.07,956.46) 1897.17,946.56 cw(c1907.07,956.46) 1893.07,956.46 1893.07,957.92 cw(c1910.61,957.92) 1898.21,970.32 cw(c1910.61,957.92) 1906.89,975.06 1906.89,983.57 cw(c1907.89,983.57) 1907.89,984.57 ccw(c1907.89,985.57) 1908.89,985.57 1908.89,998.57 ccw(c1907.89,998.57) 1907.89,999.57 cw(c1907.89,1000.57) 1906.89,1000.57 1906.89,1011.46 cw(c1908.95,1011.46) 1908.95,1013.51 ccw(c1908.95,1015.57) 1911,1015.57 1911,1026.46 ccw(c1908.95,1026.46) 1908.95,1028.51 cw(c1908.95,1030.57) 1906.89,1030.57 1906.89,1038.54 cw(c1910.4,1038.54) 1910.4,1042.05 ccw(c1910.4,1045.57) 1913.92,1045.57 1913.92,1053.54 ccw(c1910.4,1053.54) 1910.4,1057.05 cw(c1910.4,1060.57) 1906.89,1060.57 1906.89,1068.54 cw(c1910.4,1068.54) 1910.4,1072.05 ccw(c1910.4,1075.57) 1913.92,1075.57 1913.92,1083.54 ccw(c1910.4,1083.54) 1910.4,1087.05 cw(c1910.4,1090.57) 1906.89,1090.57 1906.89,1098.54 cw(c1910.4,1098.54) 1910.4,1102.05 ccw(c1910.4,1105.57) 1913.92,1105.57 1913.92,1113.54 ccw(c1910.4,1113.54) 1910.4,1117.05 cw(c1910.4,1120.57) 1906.89,1120.57 1906.89,1128.54 cw(c1910.4,1128.54) 1910.4,1132.05 ccw(c1910.4,1135.57) 1913.92,1135.57 1913.92,1143.54 ccw(c1910.4,1143.54) 1910.4,1147.05 cw(c1910.4,1150.57) 1906.89,1150.57 1906.89,1158.54 cw(c1910.4,1158.54) 1910.4,1162.05 ccw(c1910.4,1165.57) 1913.92,1165.57 1913.92,1173.54 ccw(c1910.4,1173.54) 1910.4,1177.05 cw(c1910.4,1180.57) 1906.89,1180.57 1906.89,1188.54 cw(c1910.4,1188.54) 1910.4,1192.05 ccw(c1910.4,1195.57) 1913.92,1195.57 1913.92,1203.54 ccw(c1910.4,1203.54) 1910.4,1207.05 cw(c1910.4,1210.57) 1906.89,1210.57 1906.89,1239.73 cw(c1911.45,1239.73) 1911.45,1244.29 ccw(c1911.45,1248.84) 1916,1248.84 1916,1254.73 ccw(c1911.45,1254.73) 1911.45,1259.29 cw(c1911.45,1263.84) 1906.89,1263.84 1906.89,1269.73 cw(c1911.45,1269.73) 1911.45,1274.29 ccw(c1911.45,1278.84) 1916,1278.84 1916,1284.73 ccw(c1911.45,1284.73) 1911.45,1289.29 cw(c1911.45,1293.84) 1906.89,1293.84 1906.89,1299.73 cw(c1911.45,1299.73) 1911.45,1304.29 ccw(c1911.45,1308.84) 1916,1308.84 1916,1314.73 ccw(c1911.45,1314.73) 1911.45,1319.29 cw(c1911.45,1323.84) 1906.89,1323.84 1906.89,1331.74
SDQS3P: U2.AB1 UD2.D10 | length 873.4
  Top Layer w3.5: 1899.53,771.93 1900.67,770.79 2002.61,770.79 2022.05,790.22 UD2.D10@2022.05,790.94
  Top Layer w4: U2.AB1@1883.5,1370.55 1870,1357.05 1870,1341.46 1885,1326.46 1885,1299.19 1884,1298.19
  Top Layer w5: 1884,1298.19 1884.62,1297.57 1884.62,1282.03 ccw(c1891.26,1282.03) 1891.26,1275.39 cw(c1891.26,1268.76) 1897.89,1268.76 1897.89,1267.03 cw(c1891.26,1267.03) 1891.26,1260.39 ccw(c1891.26,1253.76) 1884.62,1253.76 1884.62,1252.03 ccw(c1891.26,1252.03) 1891.26,1245.39 cw(c1891.26,1238.76) 1897.89,1238.76 1897.89,1237.03 cw(c1891.26,1237.03) 1891.26,1230.39 ccw(c1891.26,1223.76) 1884.62,1223.76 1884.62,1222.03 ccw(c1891.26,1222.03) 1891.26,1215.39 cw(c1891.26,1208.76) 1897.89,1208.76 1897.89,1207.03 cw(c1891.26,1207.03) 1891.26,1200.39 ccw(c1891.26,1193.76) 1884.62,1193.76 1884.62,1192.03 ccw(c1891.26,1192.03) 1891.26,1185.39 cw(c1891.26,1178.76) 1897.89,1178.76 1897.89,1177.03 cw(c1891.26,1177.03) 1891.26,1170.39 ccw(c1891.26,1163.76) 1884.62,1163.76 1884.62,1162.03 ccw(c1891.26,1162.03) 1891.26,1155.39 cw(c1891.26,1148.76) 1897.89,1148.76 1897.89,1147.03 cw(c1891.26,1147.03) 1891.26,1140.39 ccw(c1891.26,1133.76) 1884.62,1133.76 1884.62,1132.03 ccw(c1891.26,1132.03) 1891.26,1125.39 cw(c1891.26,1118.76) 1897.89,1118.76 1897.89,1117.03 cw(c1891.26,1117.03) 1891.26,1110.39 ccw(c1891.26,1103.76) 1884.62,1103.76 1884.62,1102.03 ccw(c1891.26,1102.03) 1891.26,1095.39 cw(c1891.26,1088.76) 1897.89,1088.76 1897.89,1087.03 cw(c1891.26,1087.03) 1891.26,1080.39 ccw(c1891.26,1073.76) 1884.62,1073.76 1884.62,1072.03 ccw(c1891.26,1072.03) 1891.26,1065.39 cw(c1891.26,1058.76) 1897.89,1058.76 1897.89,1057.03 cw(c1891.26,1057.03) 1891.26,1050.39 ccw(c1891.26,1043.76) 1884.62,1043.76 1884.62,966.61 1884.07,966.06 1884.02,803.92 1884.62,803.32 1884.62,781.84 1894.39,772.07 1899.39,772.07
SODT0: U2.AA13 UD2.J8 | length 1698.2
  Top Layer w4: v1(1976.62,684.84) 2106.89,684.84 UD2.J8@2150,727.95
  Bottom Layer w4: 1944.93,681.46 1923.73,702.65 cw(c1928.98,707.89) 1923.73,713.14 ccw(c1918.49,718.39) 1923.73,723.63 1923.62,723.75 ccw(c1918.37,718.5) 1913.13,723.75 cw(c1907.88,728.99) 1902.64,723.75 cw(c1907.94,729.05) 1902.64,734.35 1906.9,738.62 ccw(c1901.6,743.92) 1896.29,749.22 1892.03,744.96 cw(c1886.73,750.26) 1881.42,744.96 1873.5,752.88 1873.5,874.96 1922.5,923.96 1922.5,1217.37 1927.17,1222.04 1927.17,1252.94 cw(c1934.67,1252.94) 1934.67,1260.44 1947.2,1260.44 ccw(c1947.2,1267.94) 1947.2,1275.44 1934.67,1275.44 cw(c1934.67,1282.94) 1934.67,1290.44 1947.2,1290.44 ccw(c1947.2,1297.94) 1947.2,1305.44 1934.67,1305.44 cw(c1934.67,1312.94) 1927.17,1312.94 1927.17,1338.63 1930,1341.46 1943.66,1341.46 cw(c1943.66,1333.96) 1951.16,1333.96 1951.16,1325.18 ccw(c1958.66,1325.18) 1966.16,1325.18 1966.16,1333.96 cw(c1973.66,1333.96) 1981.16,1333.96 1981.16,1325.18 ccw(c1988.66,1325.18) 1996.16,1325.18 1996.16,1333.96 cw(c2003.66,1333.96) 2011.16,1333.96 2011.16,1325.18 ccw(c2018.66,1325.18) 2026.16,1325.18 2026.16,1333.96 cw(c2033.66,1333.96) 2041.16,1333.96 2041.16,1325.18 ccw(c2048.66,1325.18) 2056.16,1325.18 2056.16,1333.96 cw(c2063.66,1333.96) 2071.16,1333.96 2071.16,1325.18 ccw(c2078.66,1325.18) 2086.16,1325.18 2086.16,1333.96 cw(c2093.66,1333.96) 2101.16,1333.96 2101.16,1325.18 ccw(c2108.66,1325.18) 2116.16,1325.18 2116.16,1333.96 cw(c2123.66,1333.96) 2123.66,1341.46 2135.91,1341.46 2138.03,1343.58 ccw(c2132.72,1348.88) 2138.03,1354.18 2117.39,1374.82 cw(c2122.69,1380.13) 2127.99,1385.43 2148.63,1364.79 ccw(c2153.94,1370.09) 2159.24,1375.4 2140.6,1394.03 cw(c2145.91,1399.34) 2151.21,1404.64 2169.85,1386 2175.45,1386 v1(2185.59,1396.14) ; 1945,681.46 1973.23,681.46 v1(1976.62,684.84)
STATUS-LED: R51.1 U2.J21 | length 783.1
  Top Layer w5: U2.J21@2395.31,1703.23 2395.31,1696.14 2406.72,1684.74 2406.72,1674.74 2415.22,1666.23 2422.85,1666.23 2432.31,1656.77 2432.31,1650.15 2441,1641.46 2450,1641.46 2470,1621.46 2470,1571.46 2523,1518.46 2898,1518.46 2990,1426.46 R51.1@3020.63,1426.46
SVREF: C91.2 C111.2 C112.2 C113.2 R68.1 R69.2 U2.V6 UD2.H4 | length 1799.9
  Top Layer w5: C111.2@1826.54,1556.46 C91.2@1826.54,1516.46 1856.54,1486.46 1997.91,1486.46 U2.V6@2011.46,1472.91 ; v2(1850,456.46) 1890,416.46 C112.2@1890,414.92 1929.5,414.92 R68.1@1930,414.42 ; R69.2@1927.04,376.46 1927.04,411.46 R68.1@1930,414.42 ; UD2.H4@2124.41,601.97 2110.22,587.78 2110.22,565.75 2094.86,550.38 2068.5,550.38 2059.04,540.92 2059.04,515.7 2014.8,471.46 1965,471.46 1955,461.46 1955,439.42 R68.1@1930,414.42
  Bottom Layer w5: v2(1824.76,1516.46) 1824.76,1413.95 1781,1370.18 1781,557.73 1824.76,513.96 1824.76,481.69 v2(1850,456.46)
SVREF_DQ: C92.2 C114.2 R21.2 R22.1 UD2.J11 | length 256.2
  Top Layer w5: C92.2@2091.54,941.46 R22.1@2137.96,941.46 ; R21.2@2127.04,981.46 2137.96,970.54 R22.1@2137.96,941.46 ; UD2.J11@2150,822.44 2150,837.81 2161.41,849.21 2161.41,918.01 R22.1@2137.96,941.46
  Top Layer w6: R21.2@2127.04,981.46 2135,989.42 C114.2@2135,1009.92
TYPE-5V: C131.2 C132.1 C149.1 pad.1@390,1947.63 R39.1 R40.1 USB4.A4B9 USB4.B4A9 | length 641.1
  Top Layer w12: 237.19,2001.26 249.19,1989.26 264.46,1989.26 276.76,1976.96 USB4.B4A9@293.51,1976.97 ; 237.19,2146.46 244.38,2153.64 264.46,2153.64 276.76,2165.94 USB4.A4B9@293.51,2165.94
  Top Layer w20: v2(175.59,2021.46) 235.14,2021.46 cw(c235.14,2018.56) 237.19,2020.61 ; 237.19,2001.26 237.19,2020.61 ; 237.19,2146.46 237.19,2020.61
  Top Layer w25: v2(172.56,2086.46) 230,2086.46 ; USB4.B4A9@293.51,1976.97 294.01,1976.46 v2(390,1976.46) pad.1@390,1947.63 390,1901.46 C132.1@380,1891.46
  Bottom Layer w40: R39.1@380.63,1896.46 R40.1@380.63,1956.46
  other v2: 360,1876.46 395,1916.46 365,1941.46
UART0-RX: Q4.2 R62.2 U2.D12 | length 3067.6
  Top Layer w6: v1(2130.39,1865.8) U2.D12@2165,1831.18 ; v2(2713,1976.46) 2713,1913.46 2743.5,1882.96 3478.5,1882.96 3485,1876.46 3485,1381.46 3390,1286.46 3135,1286.46 3105,1256.46 R62.2@3099.37,1256.46
  Top Layer w10: R62.2@3099.37,1256.46 3099.37,1252.09 3140,1211.46 3203.77,1211.46 Q4.2@3257.4,1157.83
  SIG w6: v1(2130.39,1865.8) 2130.39,2126.84 2270,2266.46 2375,2266.46 2610,2031.46 2680,2031.46 2713,1998.46 v2(2713,1976.46)
UART0-TX: R61.1 U2.C9 | length 2690.2
  Top Layer w6: v1(2735,1991.46) 2735,1966.46 2723,1954.46 2723,1917.6 2747.64,1892.96 3488.5,1892.96 3505,1876.46 3505,1376.46 3425,1296.46 v2(3425,1291.46)
  SIG w5: v1(2089.41,1864.51) 2120.89,1895.98 2120.89,2130.78 2266.06,2275.96 2380.5,2275.96 2615.5,2040.96 2683.94,2040.96 2733.44,1991.46 v1(2735,1991.46)
  Bottom Layer w5: v2(3370,1191.46) 3370,1236.46 v2(3425,1291.46)
UBOOT: C143.1 R59.1 U2.G17 | length 958.1
  Top Layer w4: U2.G17@2292.95,1754.41 2342.05,1754.41 2355,1741.46 2355,1726.46 2365,1716.46 2423.1,1716.46 2479.04,1660.52 v1(2479.04,1642.42) ; v2(2925,1751.46) 2999.21,1825.66 R59.1@3016.51,1825.66
  Top Layer w6: R59.1@3016.51,1825.66 3016.51,1762.39 C143.1@3037.44,1741.46
  Bottom Layer w4: v1(2479.04,1642.42) 2815.96,1642.42 v2(2925,1751.46)
USB0-DM: U2.A13 USB2.2 | length 1047
  Bottom Layer w5: v1(2190,1911.46) 2202,1923.46 2202,2756.36 2209.36,2763.71 ccw(c2204.05,2769.02) 2209.36,2774.32 2203.19,2780.49 cw(c2208.49,2785.79) 2213.79,2791.09 2219.96,2784.93 ccw(c2225.27,2790.23) 2230.57,2795.53 2224.4,2801.7 cw(c2229.7,2807) 2235.01,2812.31 2241.18,2806.14 ; 2241.17,2806.14 ccw(c2246.48,2811.44) 2251.78,2806.14 USB2.2@2292.5,2846.86
USB0-DP: U2.B13 USB2.3 | length 1047.4
  Bottom Layer w5: v1(2190,1886.46) 2211,1907.46 2211,2747.46 2280.78,2817.24 2304.77,2817.24 2334.39,2846.86 USB2.3@2347.5,2846.86
USB0-DRVVBUS: R31.2 R34.2 U2.H20 U4.4 U7.4 | length 2229.2
  Top Layer w5: U2.H20@2369.72,1728.82 2372.65,1731.75 v1(2372.65,1734.96)
  Top Layer w8: R31.2@2159.37,2496.46 2164.37,2491.46 v2(2235,2491.46)
  SIG w8: v2(2270.05,2231.4) 2240.05,2201.4 2240.05,1921.4 2260.8,1900.65 2345.8,1900.65 2372.06,1874.39 2372.06,1735.54 v1(2372.65,1734.96)
  Bottom Layer w8: U7.4@1742.6,3201.88 1742.6,3271.53 R34.2@1732.67,3281.46 1737.67,3286.46 2075,3286.46 2115,3246.46 2115,2537.87 v2(2159.37,2493.5) ; v2(2235,2491.46) 2270.05,2456.4 v2(2270.05,2231.4)
USB1-AP-SSTXN: C23.1 U2.B15 | length 136.6
  Top Layer w5: C23.1@2215,1984.92 ccw(c2221.04,1984.92) 2216.77,1980.65 2238.14,1959.27 ; 2238.14,1959.27 cw(c2238.14,1953.24) 2242.41,1957.51 cw(c2238.14,1953.24) 2244.18,1953.24 2244.18,1942.28 cw(c2239.09,1942.28) 2239.09,1937.2 ccw(c2239.09,1932.11) 2234.01,1932.11 2234.01,1927.28 ccw(c2239.09,1927.28) 2239.09,1922.2 cw(c2239.09,1917.11) 2244.18,1917.11 2244.18,1912.28 cw(c2240.38,1912.28) 2240.38,1908.48 ccw(c2240.38,1904.69) 2236.59,1904.69 2236.59,1897.28 ccw(c2240.38,1897.28) 2240.38,1893.48 cw(c2240.38,1889.69) 2244.18,1889.69 2244.18,1884.77 U2.B15@2241.77,1882.36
